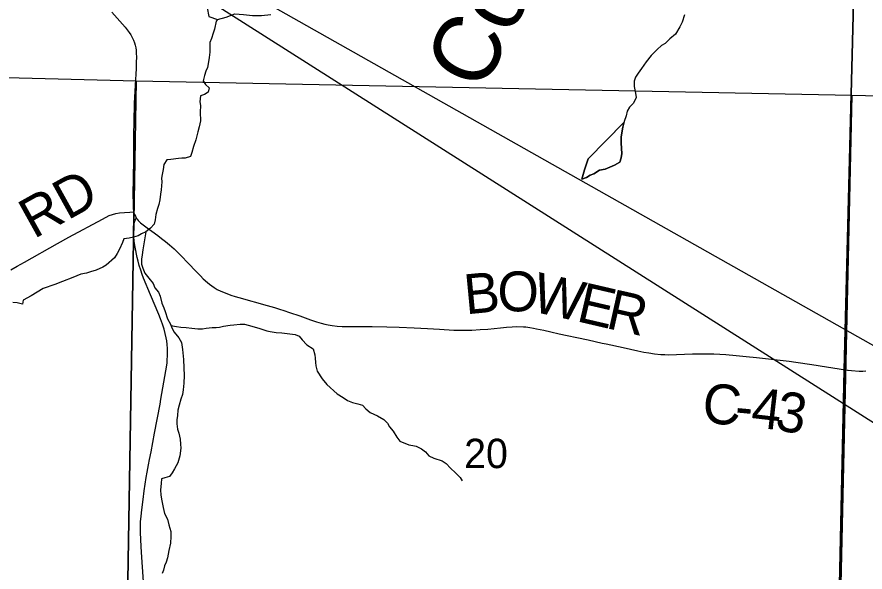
# Model space of a CAD drawing. Extents: x 0 to 34, y 0 to 22.
# Drawn here: x 5.387 to 6.594, y 16.248 to 17.039 of the extents above; entities that cross this region are included whole.
import ezdxf

# ---------------------------------------------------------------- set-up
doc = ezdxf.new("R2010")
doc.units = 0
for name, color, linetype in [('GM_X_Corporation', 7, 'Continuous'), ('GM_X_County_Road_Text', 7, 'Continuous'), ('GM_X_Interchange_Ramps', 7, 'Continuous'), ('GM_X_Interstate_Route', 7, 'Continuous'), ('GM_X_Major_Lake', 7, 'Continuous'), ('GM_X_Major_River', 7, 'Continuous'), ('GM_X_Minor_Lake', 7, 'Continuous'), ('GM_X_Section', 7, 'Continuous'), ('GM_X_Township_Road_Text', 7, 'Continuous'), ('GM_X_US_Location', 7, 'Continuous'), ('SH_Data', 7, 'Continuous')]:
    doc.layers.add(name, color=color, linetype=linetype)

msp = doc.modelspace()

# ---------------------------------------------------------------- linework, layer by layer
at = {"layer": 'GM_X_Corporation'}
for points in [[(5.5219, 17.0454), (5.5409, 17.0239), (5.5438, 17.0204), (5.5465, 17.0167), (5.5489, 17.0131), (5.5509, 17.0095), (5.5527, 17.0056), (5.5542, 17.0018), (5.5552, 16.9982), (5.556, 16.9946), (5.5565, 16.9911), (5.5568, 16.9869), (5.557, 16.9813), (5.5567, 16.9742), (5.5564, 16.9651), (5.5551, 16.9414), (5.5537, 16.9152), (5.5531, 16.8894), (5.5529, 16.8709), (5.5527, 16.8377), (5.5523, 16.8067), (5.5519, 16.788), (5.5523, 16.7702), (5.5525, 16.7657), (5.5528, 16.7626), (5.553, 16.7613), (5.5534, 16.7598), (5.5542, 16.7574), (5.5555, 16.7547), (5.5568, 16.7525), (5.5573, 16.7517), (5.558, 16.7507), (5.5596, 16.7489), (5.5606, 16.7478), (5.5629, 16.7456), (5.5664, 16.7426), (5.5724, 16.7382), (5.579, 16.7337), (5.5874, 16.7275), (5.5928, 16.7231), (5.5982, 16.719), (5.6039, 16.7141), (5.6105, 16.7084), (5.62, 16.6991), (5.631, 16.6875), (5.6415, 16.6765), (5.6481, 16.6699), (5.6522, 16.6658), (5.658, 16.6606), (5.661, 16.658), (5.6642, 16.6556), (5.6674, 16.6534), (5.6719, 16.6507), (5.677, 16.6481), (5.6833, 16.6455), (5.6914, 16.6426), (5.6977, 16.6406), (5.7028, 16.639), (5.743, 16.6279), (5.7483, 16.6265), (5.7537, 16.6248), (5.7608, 16.6227), (5.7667, 16.6207), (5.775, 16.6179), (5.7898, 16.6128), (5.8046, 16.6074), (5.8133, 16.6045), (5.82, 16.6024), (5.8251, 16.6011), (5.8302, 16.6), (5.8357, 16.5991), (5.8429, 16.5984), (5.8497, 16.598), (5.8584, 16.5978), (5.8925, 16.5977), (5.9134, 16.5972), (5.9309, 16.5967), (5.9525, 16.5958), (5.9712, 16.5948), (5.9883, 16.5939), (6.0087, 16.5926), (6.0144, 16.5924), (6.0345, 16.5926), (6.0465, 16.5933), (6.0572, 16.5941), (6.0754, 16.5958), (6.084, 16.5967), (6.0918, 16.5973), (6.0981, 16.5976), (6.1082, 16.5974), (6.1113, 16.5971), (6.1171, 16.5964), (6.1225, 16.5954), (6.1266, 16.5946), (6.1369, 16.5924), (6.147, 16.5902), (6.159, 16.5875), (6.1702, 16.5851), (6.1841, 16.582), (6.2, 16.5786), (6.2203, 16.5742), (6.2256, 16.573), (6.2501, 16.5677), (6.2709, 16.5631), (6.2793, 16.5614), (6.2865, 16.5601), (6.2947, 16.559), (6.3035, 16.5581), (6.3092, 16.5577), (6.315, 16.5576), (6.326, 16.5579), (6.3374, 16.5583), (6.3489, 16.5587), (6.3586, 16.5588), (6.3701, 16.5589), (6.3792, 16.5587), (6.3962, 16.5577), (6.4107, 16.5566), (6.4254, 16.5552), (6.4398, 16.5536), (6.4865, 16.5482), (6.4961, 16.547), (6.5188, 16.5436), (6.5696, 16.5358), (6.5705, 16.5357)], [(6.5705, 16.5357), (6.575, 16.5351), (6.586, 16.5344), (6.5914, 16.5343), (6.5957, 16.5345)]]:
    msp.add_lwpolyline(points, dxfattribs=at)
at = {"layer": 'GM_X_Interchange_Ramps'}
msp.add_lwpolyline([(2.1, 17.9098), (2.1, 14.1), (6.5113, 14.1), (6.5389, 15.3228), (6.5411, 15.4243), (6.5572, 16.1864), (6.5647, 16.5359), (6.5883, 17.471), (6.5943, 17.9356)], dxfattribs=at)
msp.add_lwpolyline([(6.5113, 14.1), (8.9, 14.1), (8.9, 17.8921), (8.5492, 17.9006), (8.3297, 17.9059), (7.6027, 17.9156), (6.5943, 17.9356), (6.5883, 17.471), (6.5647, 16.5359), (6.5572, 16.1864), (6.5411, 15.4243), (6.5389, 15.3228)], close=True, dxfattribs=at)
at = {"layer": 'GM_X_Interstate_Route'}
for points in [[(5.3781, 16.6786), (5.3873, 16.6837), (5.3976, 16.6894), (5.4446, 16.7158), (5.4607, 16.7249), (5.5085, 16.7508), (5.5181, 16.7557), (5.5227, 16.7574), (5.5274, 16.7586), (5.5329, 16.7595), (5.5398, 16.7601), (5.5475, 16.7607), (5.553, 16.7613)], [(5.5672, 16.234), (5.5642, 16.2762), (5.5635, 16.2846), (5.563, 16.2943), (5.5626, 16.3042), (5.5629, 16.3196), (5.5635, 16.3277), (5.5647, 16.3367), (5.5665, 16.3514), (5.568, 16.3637), (5.5708, 16.3829), (5.5721, 16.3904), (5.5739, 16.4007), (5.5756, 16.4086), (5.5779, 16.4195), (5.5829, 16.446), (5.5907, 16.4874), (5.5918, 16.4943), (5.599, 16.5346), (5.5997, 16.54), (5.6005, 16.5459), (5.6009, 16.55), (5.6013, 16.5563), (5.6014, 16.5617), (5.6013, 16.5665), (5.6008, 16.572), (5.6001, 16.5772), (5.5992, 16.5817), (5.5979, 16.5876), (5.5963, 16.5938), (5.594, 16.6013), (5.5914, 16.6085), (5.5887, 16.6151), (5.5772, 16.643), (5.5671, 16.6668), (5.5652, 16.6718), (5.5631, 16.6778), (5.5609, 16.6845), (5.5593, 16.6908), (5.5581, 16.6962), (5.5551, 16.7106), (5.5539, 16.7187), (5.5532, 16.7265), (5.5528, 16.733), (5.5529, 16.7407), (5.5535, 16.7436), (5.5542, 16.7465), (5.5551, 16.749), (5.5559, 16.7507), (5.5568, 16.7525)]]:
    msp.add_lwpolyline(points, dxfattribs=at)
at = {"layer": 'GM_X_Minor_Lake'}
for points in [[(4.539, 16.9739), (5.5566, 16.9477), (5.5393, 15.9226), (4.5275, 15.9394)], [(5.5566, 16.9477), (6.5754, 16.9273), (6.553, 15.9139), (5.5393, 15.9226)], [(7.5942, 16.9027), (7.5725, 15.8874), (6.553, 15.9139), (6.5754, 16.9273)]]:
    msp.add_lwpolyline(points, close=True, dxfattribs=at)
at = {"layer": 'GM_X_Township_Road_Text'}
for points in [[(6.3376, 17.0414), (6.334, 17.0314), (6.3307, 17.0245), (6.3244, 17.0141), (6.3165, 17.0075), (6.3098, 17.0006), (6.3046, 16.9978), (6.2986, 16.9924), (6.29, 16.9839), (6.2829, 16.9747), (6.2763, 16.9654), (6.2714, 16.9585), (6.2677, 16.9527), (6.2655, 16.9474), (6.2656, 16.9394), (6.2677, 16.9299), (6.2685, 16.9238), (6.2649, 16.9158), (6.2589, 16.91), (6.2559, 16.9046), (6.2541, 16.8977), (6.2516, 16.8897), (6.2494, 16.8816), (6.2474, 16.8679), (6.2471, 16.8595), (6.2476, 16.8512), (6.2481, 16.8443), (6.2474, 16.8382), (6.2452, 16.8317), (6.2377, 16.8274), (6.2246, 16.8219), (6.2163, 16.8206), (6.2084, 16.8152), (6.2031, 16.8132), (6.1979, 16.8101), (6.1911, 16.8077), (6.195, 16.8207), (6.2001, 16.8364), (6.2509, 16.8881)], [(5.6722, 17.0349), (5.6703, 17.0325), (5.6682, 17.0214), (5.6664, 17.0153), (5.6638, 17.008), (5.6616, 17.0023), (5.6617, 16.9973), (5.6615, 16.9886), (5.6604, 16.981), (5.6598, 16.9745), (5.658, 16.9664), (5.6558, 16.9615), (5.654, 16.955), (5.6522, 16.9477), (5.6553, 16.9424), (5.6607, 16.9379), (5.6589, 16.9314), (5.654, 16.9283), (5.648, 16.9263), (5.647, 16.9175), (5.6482, 16.9126), (5.6479, 16.9031), (5.6481, 16.8909), (5.6463, 16.8821), (5.6442, 16.8752), (5.6413, 16.8638), (5.6384, 16.8542), (5.6359, 16.8458), (5.6341, 16.8401), (5.6265, 16.8377), (5.6216, 16.8376), (5.6167, 16.8371), (5.6061, 16.8358), (5.6001, 16.835), (5.596, 16.8284), (5.595, 16.8212), (5.5936, 16.8143), (5.5925, 16.809), (5.5929, 16.804), (5.5927, 16.7979), (5.592, 16.7922), (5.5913, 16.7861), (5.5903, 16.7781), (5.5889, 16.7716), (5.5871, 16.7659), (5.5845, 16.7575), (5.5835, 16.7498), (5.5821, 16.7433), (5.5772, 16.7379), (5.5705, 16.7325), (5.5641, 16.7297), (5.5592, 16.727), (5.5528, 16.725), (5.5464, 16.7238), (5.5392, 16.7225), (5.537, 16.7175), (5.5326, 16.7079), (5.5297, 16.7018), (5.5256, 16.6957), (5.514, 16.6852), (5.5091, 16.6825), (5.4994, 16.6781), (5.4914, 16.6757), (5.4858, 16.6737), (5.4779, 16.6721), (5.4662, 16.6677), (5.4519, 16.6618), (5.4406, 16.6578), (5.424, 16.6519), (5.4071, 16.6417), (5.3955, 16.6351), (5.3948, 16.6298), (5.3872, 16.6315), (5.3811, 16.6322)], [(6.1911, 16.8077), (6.1979, 16.8101), (6.2031, 16.8132), (6.2084, 16.8152), (6.2163, 16.8206), (6.2246, 16.8219), (6.2377, 16.8274), (6.2452, 16.8317), (6.2474, 16.8382), (6.2481, 16.8443), (6.2476, 16.8512), (6.2471, 16.8595), (6.2474, 16.8679), (6.2494, 16.8816), (6.2513, 16.8886)], [(6.2513, 16.8886), (6.2001, 16.8364), (6.195, 16.8207), (6.1911, 16.8077)], [(5.5705, 16.7325), (5.5673, 16.7153), (5.5659, 16.7069), (5.5649, 16.6997), (5.5643, 16.6936), (5.5643, 16.6867), (5.566, 16.6807), (5.5691, 16.6738), (5.5745, 16.6667), (5.5807, 16.6588), (5.583, 16.6527), (5.5884, 16.6467), (5.5908, 16.641), (5.5932, 16.6312), (5.5959, 16.6244), (5.5979, 16.6191), (5.6011, 16.6085), (5.6053, 16.6013), (5.6073, 16.596), (5.6108, 16.5896), (5.6174, 16.5817), (5.6209, 16.5749), (5.6225, 16.565), (5.6239, 16.5509), (5.6244, 16.5391), (5.6249, 16.5281), (5.6243, 16.5171), (5.6234, 16.5075), (5.6227, 16.501), (5.6201, 16.4945), (5.6176, 16.4857), (5.6158, 16.4785), (5.6152, 16.4709), (5.6145, 16.4651), (5.6146, 16.4594), (5.6155, 16.4514), (5.6174, 16.4461), (5.6191, 16.4374), (5.6199, 16.4302), (5.62, 16.4245), (5.6187, 16.4134), (5.6158, 16.4035), (5.611, 16.395), (5.6076, 16.3893), (5.6039, 16.3843), (5.5975, 16.3823), (5.5926, 16.3807), (5.592, 16.3742), (5.5913, 16.365), (5.5918, 16.3578), (5.5931, 16.3495), (5.5951, 16.34), (5.5971, 16.3316), (5.601, 16.3233), (5.603, 16.3153), (5.6058, 16.3059), (5.6059, 16.2986), (5.6053, 16.2891), (5.6032, 16.2788), (5.6014, 16.2685), (5.5993, 16.2624), (5.5971, 16.257), (5.5953, 16.2509), (5.5934, 16.2459)], [(5.6061, 16.5992), (5.6141, 16.598), (5.6202, 16.5969), (5.6277, 16.5963), (5.6357, 16.5953), (5.6444, 16.5943), (5.6512, 16.5947), (5.6562, 16.5952), (5.6648, 16.5965), (5.6705, 16.5966), (5.6754, 16.597), (5.6807, 16.5982), (5.6905, 16.5999), (5.6958, 16.6004), (5.7045, 16.6012), (5.7106, 16.6013), (5.7159, 16.5995), (5.7311, 16.5952), (5.7425, 16.5915), (5.7475, 16.5905), (5.7558, 16.5891), (5.7641, 16.5888), (5.7714, 16.5878), (5.7831, 16.5864), (5.7888, 16.5842), (5.7931, 16.579), (5.7996, 16.5718), (5.8084, 16.5659), (5.8112, 16.5575), (5.8116, 16.5526), (5.8117, 16.5465), (5.8125, 16.5416), (5.8145, 16.5344), (5.8215, 16.5234), (5.8281, 16.5152), (5.843, 16.502), (5.8514, 16.4968), (5.8575, 16.4924), (5.8644, 16.4898), (5.872, 16.4876), (5.8788, 16.4858), (5.8835, 16.4806), (5.8896, 16.4753), (5.9003, 16.4705), (5.9094, 16.4654), (5.9144, 16.4601), (5.9175, 16.4548), (5.9225, 16.4488), (5.9276, 16.4401), (5.9322, 16.4345), (5.9448, 16.4293), (5.9505, 16.4283), (5.9554, 16.4272), (5.9627, 16.4235), (5.9684, 16.4194), (5.9734, 16.4138), (5.9803, 16.4105), (5.9924, 16.4064), (5.9982, 16.4027), (6.0043, 16.396), (6.0112, 16.3892), (6.0178, 16.3828), (6.0209, 16.3779)]]:
    msp.add_lwpolyline(points, dxfattribs=at)
at = {"layer": 'GM_X_US_Location'}
msp.add_lwpolyline([(5.6521, 17.1546), (5.6511, 17.1424), (5.6554, 17.1296), (5.6643, 17.1172), (5.669, 17.1043), (5.6677, 17.091), (5.6637, 17.0762), (5.6604, 17.064), (5.6579, 17.0514), (5.66, 17.0393), (5.6722, 17.0349), (5.6847, 17.0381), (5.6971, 17.0432), (5.7093, 17.0422), (5.7222, 17.0405), (5.7351, 17.0406), (5.7484, 17.0423)], dxfattribs=at)
at = {"layer": 'SH_Data'}
msp.add_lwpolyline([(9.2998, 15.0505), (5.0551, 17.4465), (9.2998, 14.751)], close=True, dxfattribs=at)

# ---------------------------------------------------------------- texts
at = {"layer": 'GM_X_County_Road_Text'}
msp.add_text('20', height=0.04186, rotation=0, dxfattribs=at).set_placement((6.0236, 16.3961))
at = {"layer": 'GM_X_Major_Lake'}
for s, rotation, p in [('B', 5.445, (6.026, 16.615)), ('O', 0.1785, (6.0711, 16.6193)), ('W', 347.5603, (6.1178, 16.6198)), ('E', 346.8836, (6.1819, 16.6057)), ('R', 347.3633, (6.2238, 16.5959)), ('C', 354.9232, (6.3612, 16.4611)), ('4', 353.5334, (6.4306, 16.4548)), ('3', 350.4855, (6.4645, 16.4509)), ('-', 354.5978, (6.4076, 16.4569))]:
    msp.add_text(s, height=0.0568, rotation=rotation, dxfattribs=at).set_placement(p)
at = {"layer": 'GM_X_Major_River'}
msp.add_text('Conotton', height=0.09472, rotation=63.5646, dxfattribs=at).set_placement((6.0492, 16.9292))
at = {"layer": 'GM_X_Section'}
msp.add_text('RD', height=0.05682, rotation=29.0129, dxfattribs=at).set_placement((5.4109, 16.7219))

doc.saveas('drawing.dxf')
